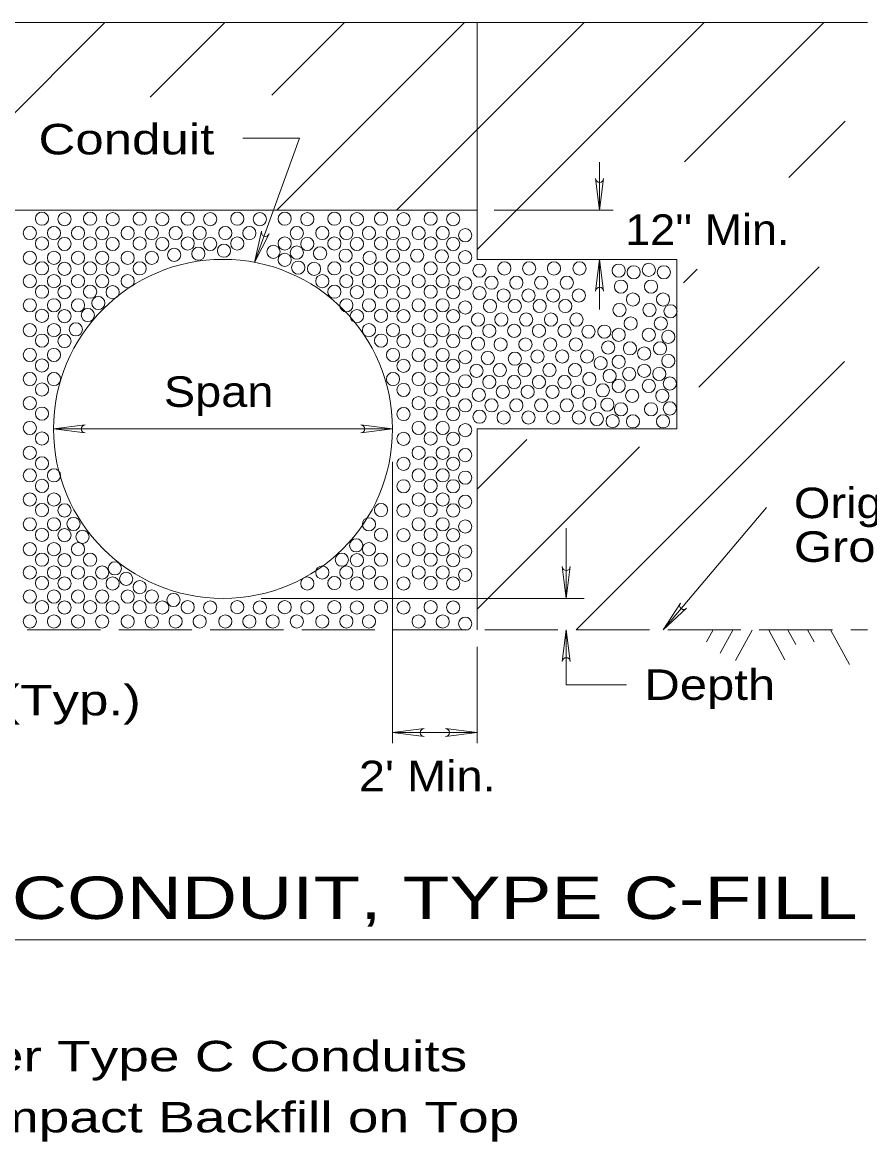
# Model space of a CAD drawing. Extents: x 750.7 to 784.7, y 834.8 to 878.8.
# Drawn here: x 775.66 to 780.66, y 846.04 to 852.64 of the extents above; entities that cross this region are included whole.
import ezdxf

# ---------------------------------------------------------------- set-up
doc = ezdxf.new("R2010")
doc.units = 0
doc.header["$LTSCALE"] = 0.072
doc.linetypes.add('LONG_DASHED', pattern=[7.5, 6, -1.5])
doc.layers.add('1', color=7, linetype='Continuous', lineweight=13)
doc.layers.add('47', color=7, linetype='Continuous', lineweight=13)

msp = doc.modelspace()

# ---------------------------------------------------------------- linework, layer by layer
at = {"layer": '1'}
for p, q in [((773.52717, 852.63842), (780.6465, 852.63842)), ((774.74817, 851.24025), (776.14617, 852.63842)), ((776.413, 852.19808), (776.85325, 852.63842)), ((777.1305, 852.2085), (777.56033, 852.63842)), ((777.15933, 851.53025), (778.26742, 852.63842)), ((777.86633, 851.53025), (778.97442, 852.63842)), ((778.34258, 851.2995), (779.6815, 852.63842)), ((778.34258, 852.63842), (778.34258, 851.24025)), ((779.56533, 851.81508), (780.38858, 852.63842)), ((780.1815, 851.72417), (780.51367, 852.05642)), ((779.065, 851.53025), (779.065, 851.81442)), ((775.34258, 851.53025), (778.34258, 851.53025)), ((778.44358, 851.53025), (779.14492, 851.53025)), ((778.34258, 851.24025), (779.52142, 851.24025)), ((779.065, 850.94408), (779.065, 851.24025)), ((779.65067, 850.48617), (780.36108, 851.19667)), ((779.55908, 851.10175), (779.63992, 851.18258)), ((778.927, 849.05517), (780.5105, 850.63883)), ((775.84258, 850.2405), (777.84258, 850.2405)), ((778.34258, 850.2405), (778.34258, 849.05517)), ((778.34258, 849.88508), (778.63575, 850.17833)), ((778.34258, 849.17792), (779.3, 850.1355)), ((777.84258, 850.04683), (777.84258, 848.38733)), ((779.43925, 849.05517), (780.05033, 849.77708)), ((778.86792, 849.2405), (778.86792, 849.65425)), ((777.06817, 849.2405), (778.9745, 849.2405)), ((779.73592, 849.05517), (779.69658, 848.98383)), ((779.8525, 849.05658), (779.77558, 848.91717)), ((779.96458, 849.05267), (779.86592, 848.87383)), ((780.0625, 849.05267), (780.15833, 848.879)), ((780.17458, 849.05658), (780.22317, 848.9685)), ((780.29117, 849.05517), (780.3305, 848.98383)), ((780.4275, 849.05567), (780.54008, 848.85158)), ((778.34258, 848.95567), (778.34258, 848.38733)), ((777.84258, 848.4495), (778.34258, 848.4495)), ((773.48175, 847.22583), (780.63675, 847.22583))]:
    msp.add_line(p, q, dxfattribs=at)
at = {"layer": '1', "linetype": 'LONG_DASHED'}
msp.add_line((773.52717, 849.05517), (780.6465, 849.05517), dxfattribs=at)
at = {"layer": '1'}
for points in [[(776.959, 851.956), (777.29367, 851.956), (777.02867, 851.223)], [(778.34258, 850.2405), (779.52142, 850.2405), (779.52142, 851.24025)], [(778.86792, 849.05517), (778.86792, 848.73075), (779.223, 848.73075)]]:
    msp.add_lwpolyline(points, dxfattribs=at)
for centre, radius in [((775.77408, 851.48039), 0.03892), ((775.90724, 851.47806), 0.03892), ((776.05816, 851.48039), 0.03892), ((776.19133, 851.47806), 0.03892), ((776.35108, 851.48039), 0.03892), ((776.48424, 851.47806), 0.03892), ((776.63416, 851.48039), 0.03892), ((776.76733, 851.47806), 0.03892), ((776.92708, 851.48039), 0.03892), ((777.06024, 851.47806), 0.03892), ((777.20674, 851.48039), 0.03892), ((777.33991, 851.47806), 0.03892), ((777.49966, 851.48039), 0.03892), ((777.63283, 851.47806), 0.03892), ((777.77491, 851.48039), 0.03892), ((777.90808, 851.47806), 0.03892), ((778.06783, 851.48039), 0.03892), ((778.20099, 851.47806), 0.03892), ((775.70305, 851.39603), 0.03892), ((775.84508, 851.39606), 0.03892), ((775.98713, 851.39603), 0.03892), ((776.12916, 851.39606), 0.03892), ((776.28005, 851.39603), 0.03892), ((776.42208, 851.39606), 0.03892), ((776.56313, 851.39603), 0.03892), ((776.70516, 851.39606), 0.03892), ((776.85605, 851.39603), 0.03892), ((776.99808, 851.39606), 0.03892), ((777.27774, 851.39606), 0.03892), ((777.42863, 851.39603), 0.03892), ((777.57066, 851.39606), 0.03892), ((777.70388, 851.39603), 0.03892), ((777.84591, 851.39606), 0.03892), ((777.9968, 851.39603), 0.03892), ((778.13883, 851.39606), 0.03892), ((778.27199, 851.38272), 0.03892), ((775.77408, 851.33389), 0.03892), ((775.90724, 851.33156), 0.03892), ((776.05816, 851.33389), 0.03892), ((776.19133, 851.33156), 0.03892), ((776.35108, 851.33389), 0.03892), ((776.48424, 851.33156), 0.03892), ((776.63416, 851.33389), 0.03892), ((776.76733, 851.33156), 0.03892), ((776.84817, 851.29154), 0.03892), ((776.92708, 851.33389), 0.03892), ((777.14011, 851.28498), 0.03892), ((777.20674, 851.33389), 0.03892), ((777.33991, 851.33156), 0.03892), ((777.49966, 851.33389), 0.03892), ((777.63283, 851.33156), 0.03892), ((777.77491, 851.33389), 0.03892), ((777.90808, 851.33156), 0.03892), ((778.06783, 851.33389), 0.03892), ((778.20099, 851.33156), 0.03892), ((775.70305, 851.24944), 0.03892), ((775.84508, 851.24947), 0.03892), ((775.98713, 851.24944), 0.03892), ((776.12916, 851.24947), 0.03892), ((776.28005, 851.24944), 0.03892), ((776.42208, 851.24947), 0.03892), ((776.55423, 851.26725), 0.03892), ((776.69733, 851.27379), 0.03892), ((777.20668, 851.23829), 0.03892), ((777.27778, 851.28049), 0.03892), ((777.41536, 851.27607), 0.03892), ((777.56628, 851.26274), 0.03892), ((777.70828, 851.2494), 0.03892), ((777.84586, 851.26274), 0.03892), ((777.98795, 851.26274), 0.03892), ((778.13436, 851.25832), 0.03892), ((778.27195, 851.25382), 0.03892), ((775.77408, 851.18731), 0.03892), ((776.84258, 850.2405), 1), ((775.90724, 851.18497), 0.03892), ((776.05816, 851.18731), 0.03892), ((776.19133, 851.18497), 0.03892), ((776.35108, 851.18731), 0.03892), ((777.28664, 851.1917), 0.03892), ((777.37984, 851.18495), 0.03892), ((777.49966, 851.18731), 0.03892), ((777.63283, 851.18497), 0.03892), ((777.77491, 851.18731), 0.03892), ((777.90808, 851.18497), 0.03892), ((778.06783, 851.18731), 0.03892), ((778.20099, 851.18497), 0.03892), ((778.35628, 851.1739), 0.03892), ((778.50278, 851.18724), 0.03892), ((778.6492, 851.18724), 0.03892), ((778.7957, 851.18724), 0.03892), ((778.94661, 851.18724), 0.03892), ((779.17737, 851.17391), 0.03892), ((779.2662, 851.16415), 0.03892), ((779.35487, 851.17833), 0.03892), ((779.4437, 851.16415), 0.03892), ((775.70305, 851.11178), 0.03892), ((775.84508, 851.11181), 0.03892), ((775.98713, 851.11178), 0.03892), ((776.12916, 851.11181), 0.03892), ((776.28005, 851.11178), 0.03892), ((777.42863, 851.11178), 0.03892), ((777.57066, 851.11181), 0.03892), ((777.70388, 851.11178), 0.03892), ((777.84591, 851.11181), 0.03892), ((777.9968, 851.11178), 0.03892), ((778.13883, 851.11181), 0.03892), ((778.27199, 851.09847), 0.03892), ((778.42736, 851.1029), 0.03892), ((778.57378, 851.1029), 0.03892), ((778.72028, 851.1029), 0.03892), ((778.8712, 851.1029), 0.03892), ((775.77408, 851.04964), 0.03892), ((775.90724, 851.04731), 0.03892), ((776.05816, 851.04964), 0.03892), ((776.19133, 851.04731), 0.03892), ((777.49966, 851.04964), 0.03892), ((777.63283, 851.04731), 0.03892), ((777.77491, 851.04964), 0.03892), ((777.90808, 851.04731), 0.03892), ((778.06783, 851.04964), 0.03892), ((778.20099, 851.04731), 0.03892), ((778.35628, 851.04074), 0.03892), ((778.49836, 851.0274), 0.03892), ((778.64478, 851.0274), 0.03892), ((778.79128, 851.0274), 0.03892), ((778.9422, 851.0274), 0.03892), ((779.19078, 851.07982), 0.03892), ((779.36828, 851.07982), 0.03892), ((775.70305, 850.96969), 0.03892), ((775.84508, 850.96972), 0.03892), ((775.98713, 850.96969), 0.03892), ((776.10692, 850.98305), 0.03892), ((777.57066, 850.96972), 0.03892), ((777.70388, 850.96969), 0.03892), ((777.84591, 850.96972), 0.03892), ((777.9968, 850.96969), 0.03892), ((778.13883, 850.96972), 0.03892), ((778.27199, 850.95639), 0.03892), ((778.41845, 850.96524), 0.03892), ((778.56486, 850.96524), 0.03892), ((778.71136, 850.96524), 0.03892), ((778.86228, 850.96524), 0.03892), ((779.26178, 851.00432), 0.03892), ((779.43928, 851.00432), 0.03892), ((775.77408, 850.90756), 0.03892), ((775.90724, 850.90522), 0.03892), ((776.04483, 850.91202), 0.03892), ((777.63283, 850.90522), 0.03892), ((777.77491, 850.90756), 0.03892), ((777.90808, 850.90522), 0.03892), ((778.06783, 850.90756), 0.03892), ((778.20099, 850.90522), 0.03892), ((779.18186, 850.94215), 0.03892), ((779.35936, 850.94215), 0.03892), ((779.48362, 850.93416), 0.03892), ((775.70305, 850.82319), 0.03892), ((775.84508, 850.82322), 0.03892), ((775.97384, 850.82761), 0.03892), ((777.70388, 850.82319), 0.03892), ((777.84591, 850.82322), 0.03892), ((777.9968, 850.82319), 0.03892), ((778.13883, 850.82322), 0.03892), ((778.34745, 850.88532), 0.03892), ((778.48503, 850.88532), 0.03892), ((778.63145, 850.88532), 0.03892), ((778.77795, 850.88532), 0.03892), ((778.92886, 850.88532), 0.03892), ((779.24845, 850.86224), 0.03892), ((779.42595, 850.86224), 0.03892), ((775.77408, 850.76106), 0.03892), ((775.90724, 850.75872), 0.03892), ((777.77491, 850.76106), 0.03892), ((777.90808, 850.75872), 0.03892), ((778.06783, 850.76106), 0.03892), ((778.20099, 850.75872), 0.03892), ((778.27199, 850.80989), 0.03892), ((778.41403, 850.81874), 0.03892), ((778.56045, 850.81874), 0.03892), ((778.70695, 850.81874), 0.03892), ((778.85786, 850.81874), 0.03892), ((778.99978, 850.81425), 0.03892), ((779.09303, 850.81425), 0.03892), ((779.17745, 850.79565), 0.03892), ((779.35495, 850.79565), 0.03892), ((779.47028, 850.78316), 0.03892), ((778.34745, 850.74324), 0.03892), ((778.48061, 850.73882), 0.03892), ((778.62703, 850.73882), 0.03892), ((778.77353, 850.73882), 0.03892), ((778.92445, 850.73882), 0.03892), ((779.1152, 850.721), 0.03892), ((779.24403, 850.71574), 0.03892), ((779.42153, 850.71574), 0.03892), ((775.70305, 850.67661), 0.03892), ((775.84508, 850.67664), 0.03892), ((777.84591, 850.67664), 0.03892), ((777.9968, 850.67661), 0.03892), ((778.13883, 850.67664), 0.03892), ((778.27199, 850.66331), 0.03892), ((778.40511, 850.6589), 0.03892), ((778.56487, 850.65441), 0.03892), ((778.69795, 850.66775), 0.03892), ((778.84445, 850.66775), 0.03892), ((778.99095, 850.66775), 0.03892), ((779.07078, 850.62775), 0.03892), ((779.17737, 850.63666), 0.03892), ((779.32828, 850.6855), 0.03892), ((779.47028, 850.64108), 0.03892), ((775.77408, 850.61447), 0.03892), ((777.90808, 850.61214), 0.03892), ((778.06783, 850.61447), 0.03892), ((778.20099, 850.61214), 0.03892), ((778.33853, 850.5834), 0.03892), ((778.47611, 850.58782), 0.03892), ((778.62253, 850.58782), 0.03892), ((778.76903, 850.58782), 0.03892), ((778.91995, 850.58782), 0.03892), ((779.23953, 850.56474), 0.03892), ((779.32828, 850.58341), 0.03892), ((779.41703, 850.56474), 0.03892), ((775.70305, 850.53461), 0.03892), ((775.84508, 850.53464), 0.03892), ((777.84591, 850.53464), 0.03892), ((777.9968, 850.53461), 0.03892), ((778.13883, 850.53464), 0.03892), ((778.27199, 850.52131), 0.03892), ((778.41403, 850.51682), 0.03892), ((778.56045, 850.51682), 0.03892), ((778.70695, 850.51682), 0.03892), ((778.85786, 850.51682), 0.03892), ((779.00428, 850.53458), 0.03892), ((779.12412, 850.55233), 0.03892), ((779.17745, 850.49374), 0.03892), ((779.35495, 850.49374), 0.03892), ((779.4792, 850.50791), 0.03892), ((775.77408, 850.47247), 0.03892), ((777.90808, 850.47014), 0.03892), ((778.06783, 850.47247), 0.03892), ((778.20099, 850.47014), 0.03892), ((778.35186, 850.44132), 0.03892), ((778.49395, 850.45907), 0.03892), ((778.64036, 850.45907), 0.03892), ((778.78686, 850.45907), 0.03892), ((778.93778, 850.45907), 0.03892), ((779.08412, 850.46791), 0.03892), ((779.25736, 850.43599), 0.03892), ((779.43486, 850.43599), 0.03892), ((775.70305, 850.39253), 0.03892), ((777.9968, 850.39253), 0.03892), ((778.13883, 850.39256), 0.03892), ((778.27199, 850.37922), 0.03892), ((778.42736, 850.37915), 0.03892), ((778.57378, 850.37915), 0.03892), ((778.72028, 850.37915), 0.03892), ((778.8712, 850.37915), 0.03892), ((779.00428, 850.388), 0.03892), ((779.11078, 850.38358), 0.03892), ((779.4792, 850.36141), 0.03892), ((775.77408, 850.33039), 0.03892), ((777.90808, 850.32806), 0.03892), ((778.06783, 850.33039), 0.03892), ((778.20099, 850.32806), 0.03892), ((778.35628, 850.31257), 0.03892), ((778.49836, 850.30807), 0.03892), ((778.64478, 850.30807), 0.03892), ((778.79128, 850.30807), 0.03892), ((778.9422, 850.30807), 0.03892), ((779.04862, 850.29925), 0.03892), ((779.19078, 850.35607), 0.03892), ((779.36828, 850.35607), 0.03892), ((775.70305, 850.24603), 0.03892), ((777.9968, 850.24603), 0.03892), ((778.13883, 850.24606), 0.03892), ((778.27199, 850.23272), 0.03892), ((779.14187, 850.28591), 0.03892), ((779.26178, 850.28499), 0.03892), ((779.43928, 850.28499), 0.03892), ((775.77408, 850.18389), 0.03892), ((777.90808, 850.18156), 0.03892), ((778.06783, 850.18389), 0.03892), ((778.20099, 850.18156), 0.03892), ((775.70305, 850.09944), 0.03892), ((777.9968, 850.09944), 0.03892), ((778.13883, 850.09947), 0.03892), ((775.77408, 850.03731), 0.03892), ((777.90808, 850.03497), 0.03892), ((778.06783, 850.03731), 0.03892), ((778.20099, 850.03497), 0.03892), ((778.27199, 850.08614), 0.03892), ((775.70305, 849.96628), 0.03892), ((775.84508, 849.96631), 0.03892), ((777.9968, 849.96628), 0.03892), ((778.13883, 849.96631), 0.03892), ((775.77408, 849.90414), 0.03892), ((777.90808, 849.90181), 0.03892), ((778.06783, 849.90414), 0.03892), ((778.20099, 849.90181), 0.03892), ((778.27199, 849.95297), 0.03892), ((775.70305, 849.82419), 0.03892), ((775.84508, 849.82422), 0.03892), ((777.9968, 849.82419), 0.03892), ((778.13883, 849.82422), 0.03892), ((778.27199, 849.81089), 0.03892), ((775.77408, 849.76206), 0.03892), ((775.90724, 849.75972), 0.03892), ((777.77491, 849.76206), 0.03892), ((777.90808, 849.75972), 0.03892), ((778.06783, 849.76206), 0.03892), ((778.20099, 849.75972), 0.03892), ((775.70305, 849.67769), 0.03892), ((775.84508, 849.67772), 0.03892), ((775.9605, 849.67979), 0.03892), ((777.70388, 849.67769), 0.03892), ((777.9968, 849.67769), 0.03892), ((778.13883, 849.67772), 0.03892), ((778.27199, 849.66439), 0.03892), ((775.77408, 849.61556), 0.03892), ((775.90724, 849.61322), 0.03892), ((776.01375, 849.60429), 0.03892), ((777.77491, 849.61556), 0.03892), ((777.90808, 849.61322), 0.03892), ((778.06783, 849.61556), 0.03892), ((778.20099, 849.61322), 0.03892), ((775.70305, 849.53111), 0.03892), ((775.84508, 849.53114), 0.03892), ((775.98713, 849.53111), 0.03892), ((777.62835, 849.55334), 0.03892), ((777.70388, 849.53111), 0.03892), ((777.9968, 849.53111), 0.03892), ((778.13883, 849.53114), 0.03892), ((778.27199, 849.51781), 0.03892), ((775.77408, 849.46897), 0.03892), ((775.90724, 849.46664), 0.03892), ((776.05816, 849.46897), 0.03892), ((777.54401, 849.46892), 0.03892), ((777.63283, 849.46664), 0.03892), ((777.77491, 849.46897), 0.03892), ((777.90808, 849.46664), 0.03892), ((778.06783, 849.46897), 0.03892), ((778.20099, 849.46664), 0.03892), ((775.70305, 849.39344), 0.03892), ((775.84508, 849.39347), 0.03892), ((775.98713, 849.39344), 0.03892), ((776.12916, 849.39347), 0.03892), ((776.20458, 849.41787), 0.03892), ((777.42863, 849.39344), 0.03892), ((777.57066, 849.39347), 0.03892), ((777.70388, 849.39344), 0.03892), ((777.9968, 849.39344), 0.03892), ((778.13883, 849.39347), 0.03892), ((778.27199, 849.38014), 0.03892), ((775.77408, 849.33131), 0.03892), ((775.90724, 849.32897), 0.03892), ((776.05816, 849.33131), 0.03892), ((776.19133, 849.32897), 0.03892), ((776.27117, 849.35571), 0.03892), ((776.35108, 849.30679), 0.03892), ((777.33991, 849.32897), 0.03892), ((777.49966, 849.33131), 0.03892), ((777.63283, 849.32897), 0.03892), ((777.77491, 849.33131), 0.03892), ((777.90808, 849.32897), 0.03892), ((778.06783, 849.33131), 0.03892), ((778.20099, 849.32897), 0.03892), ((775.70305, 849.25136), 0.03892), ((775.84508, 849.25139), 0.03892), ((775.98713, 849.25136), 0.03892), ((776.12916, 849.25139), 0.03892), ((776.28005, 849.25136), 0.03892), ((776.42208, 849.25139), 0.03892), ((775.77408, 849.18922), 0.03892), ((775.90724, 849.18689), 0.03892), ((776.05816, 849.18922), 0.03892), ((776.19133, 849.18689), 0.03892), ((776.35108, 849.18922), 0.03892), ((776.48424, 849.18689), 0.03892), ((776.55083, 849.23137), 0.03892), ((776.63416, 849.18922), 0.03892), ((776.76733, 849.18689), 0.03892), ((776.92708, 849.18922), 0.03892), ((777.06024, 849.18689), 0.03892), ((777.20674, 849.18922), 0.03892), ((777.33991, 849.18689), 0.03892), ((777.49966, 849.18922), 0.03892), ((777.63283, 849.18689), 0.03892), ((777.77491, 849.18922), 0.03892), ((777.90808, 849.18689), 0.03892), ((778.06783, 849.18922), 0.03892), ((778.20099, 849.18689), 0.03892), ((775.70305, 849.10486), 0.03892), ((775.84508, 849.10489), 0.03892), ((775.98713, 849.10486), 0.03892), ((776.12916, 849.10489), 0.03892), ((776.28005, 849.10486), 0.03892), ((776.42208, 849.10489), 0.03892), ((776.56313, 849.10486), 0.03892), ((776.70516, 849.10489), 0.03892), ((776.85605, 849.10486), 0.03892), ((776.99808, 849.10489), 0.03892), ((777.13571, 849.10486), 0.03892), ((777.27774, 849.10489), 0.03892), ((777.42863, 849.10486), 0.03892), ((777.57066, 849.10489), 0.03892), ((777.70388, 849.10486), 0.03892), ((777.9968, 849.10486), 0.03892), ((778.13883, 849.10489), 0.03892), ((778.27199, 849.09156), 0.03892)]:
    msp.add_circle(centre, radius, dxfattribs=at)
at = {"layer": '47'}
for points in [[(779.08842, 851.71775), (779.065, 851.53025), (779.04158, 851.71775)], [(777.11442, 851.39133), (777.02867, 851.223), (777.07042, 851.40733)], [(779.04158, 851.05275), (779.065, 851.24025), (779.08842, 851.05275)], [(776.03008, 850.21708), (775.84258, 850.2405), (776.03008, 850.26392)], [(777.65508, 850.26392), (777.84258, 850.2405), (777.65508, 850.21708)], [(778.89133, 849.428), (778.86792, 849.2405), (778.8445, 849.428)], [(779.57825, 849.18317), (779.43925, 849.05517), (779.5425, 849.21342)], [(778.8445, 848.86767), (778.86792, 849.05517), (778.89133, 848.86767)], [(778.03008, 848.42608), (777.84258, 848.4495), (778.03008, 848.47292)], [(778.15508, 848.47292), (778.34258, 848.4495), (778.15508, 848.42608)]]:
    msp.add_lwpolyline(points, dxfattribs=at)
for centre, start, end in [((779.06499, 851.71776), 180, 0), ((777.09241, 851.39934), 160.12536, 340.12536), ((779.06501, 851.05274), 0, 180), ((776.03009, 850.24051), 90, 270), ((777.65508, 850.24049), 270, 90), ((778.86791, 849.42801), 180, 0), ((779.56039, 849.19829), 139.75297, 319.75297), ((778.86792, 848.86766), 0, 180), ((778.03009, 848.44951), 90, 270), ((778.15508, 848.44949), 270, 90)]:
    msp.add_arc(centre, 0.02342, start, end, dxfattribs=at)

# ---------------------------------------------------------------- texts
at = {"layer": '1'}
for s, height, width, p in [('Conduit', 0.18, 1.25, (775.754, 851.85958)), ("12'' Min.", 0.18, 1.1, (779.21592, 851.32583)), ('Span', 0.18, 1.15, (776.49342, 850.37042)), ('Original', 0.18, 1.15, (780.21158, 849.71408)), ('Ground', 0.18, 1.2, (780.21158, 849.45608)), ('Depth', 0.18, 1.2, (779.32958, 848.64192)), ('0.5 X Span (Typ.)', 0.18, 1.3, (773.90567, 848.55075)), ("2' Min.", 0.18, 1.15, (777.64467, 848.10317)), ('PLASTIC CONDUIT, TYPE C-FILL', 0.25, 1.35, (773.59017, 847.34992)), ('** For All Other Type C Conduits', 0.18, 1.35, (773.58825, 846.45075)), ('   Place & Compact Backfill on Top', 0.18, 1.35, (773.58825, 846.09075))]:
    msp.add_text(s, height=height, dxfattribs=dict(at, width=width)).set_placement(p)

doc.saveas('drawing.dxf')
